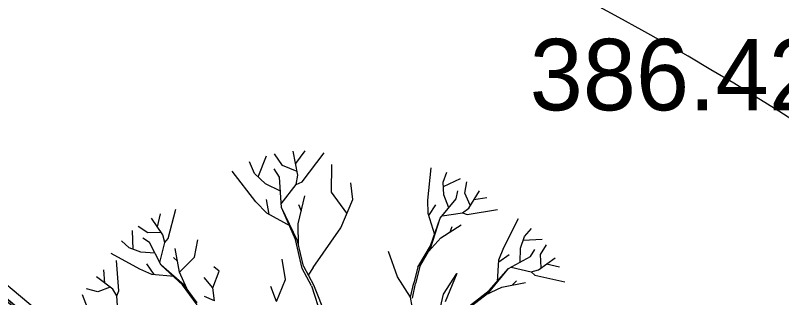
# Model space of a CAD drawing. Extents: x -438233 to -437334, y -1133133 to -1132623.
# Drawn here: x -438141.5 to -438133.46, y -1132955.36 to -1132952.39 of the extents above; entities that cross this region are included whole.
import ezdxf

# ---------------------------------------------------------------- set-up
doc = ezdxf.new("R2010")
doc.units = 0
for name, color, linetype in [('MOBILIÁŘ', 7, 'Continuous'), ('Vrstva 1', 7, 'Continuous'), ('Vrstva 10', 7, 'Continuous'), ('Vrstva 11', 7, 'Continuous'), ('Vrstva 3', 7, 'Continuous')]:
    doc.layers.add(name, color=color, linetype=linetype)

# ---------------------------------------------------------------- blocks, each defined once
blk = doc.blocks.new('A$C6FF56919')
at = {"layer": 'Vrstva 1'}
for p, q in [((-17605, 5482), (-17605, 7031)), ((-401, 7031), (-401, 5482)), ((0, 7031), (-401, 7031)), ((0, 5482), (0, 7031)), ((-18000, 5423), (-18000, 5482)), ((-18000, 5482), (-17605, 5482)), ((-18000, 5423), (0, 5423)), ((-18000, 5108), (-18000, 5423)), ((-18000, 5108), (0, 5108)), ((-18000, 4771), (-18000, 5108)), ((-17605, 5423), (-17605, 5482)), ((-401, 5482), (0, 5482)), ((-401, 5423), (-401, 5482)), ((0, 5423), (0, 5482)), ((0, 5423), (0, 5108)), ((0, 5108), (0, 4771)), ((-18000, 4771), (0, 4771)), ((-18000, 4707), (-18000, 4771)), ((0, 4707), (-18000, 4707)), ((-18000, 4707), (-18000, 4365)), ((-18000, 459), (-18000, 4365)), ((-18000, 4365), (0, 4365)), ((-17605, 459), (-17605, 4365)), ((-401, 459), (-401, 4365)), ((0, 4771), (0, 4707)), ((0, 4365), (0, 4707)), ((0, 459), (0, 4365)), ((-17605, 3703), (-17594, 3703)), ((-17594, 2805), (-17594, 3895)), ((-401, 3703), (-411, 3703)), ((-17605, 2907), (-17594, 2907)), ((-17605, 2901), (-17594, 2901)), ((-411, 2805), (-17594, 2805)), ((-17594, 2805), (-17594, 2762)), ((-17594, 2762), (-411, 2762)), ((-17594, 2575), (-411, 2575)), ((-17594, 1475), (-17594, 2575)), ((-9200, 2575), (-9200, 2762)), ((-8799, 2575), (-8799, 2762)), ((-401, 2907), (-411, 2907)), ((-401, 2901), (-411, 2901)), ((-411, 2762), (-411, 2805)), ((-411, 2575), (-411, 1475)), ((-17605, 2410), (-17594, 2410)), ((-401, 2410), (-411, 2410)), ((-17605, 1608), (-17594, 1608)), ((-17605, 1608), (-17594, 1608)), ((-17605, 1106), (-17594, 1106)), ((-17605, 1106), (-17594, 1106)), ((-17594, 1459), (-17594, 1475)), ((-17594, 1475), (-411, 1475)), ((-411, 1459), (-17594, 1459)), ((-17594, 1245), (-17594, 1256)), ((-17594, 1256), (-411, 1256)), ((-17594, 1245), (-17594, 144)), ((-411, 1245), (-17594, 1245)), ((-9200, 1256), (-9200, 1459)), ((-8800, 1256), (-8800, 1459)), ((-401, 1608), (-411, 1608)), ((-401, 1608), (-411, 1608)), ((-411, 1475), (-411, 1459)), ((-411, 1256), (-411, 1245)), ((-411, 144), (-411, 1245)), ((-401, 1106), (-411, 1106)), ((-401, 1106), (-411, 1106)), ((-18000, 459), (-18000, 0)), ((-17605, 459), (-18000, 459)), ((-18000, 0), (-17605, 0)), ((-17605, 0), (-17605, 459)), ((-17605, 305), (-17594, 305)), ((-17594, 144), (-411, 144)), ((-401, 305), (-411, 305)), ((-401, 459), (0, 459)), ((-401, 0), (-401, 459)), ((0, 0), (-401, 0)), ((0, 459), (0, 0))]:
    blk.add_line(p, q, dxfattribs=at)
for points in [[(-17605, 7031), (-18000, 7031), (-18000, 5482)], [(-17594, 3895), (-411, 3895), (-411, 2805)]]:
    blk.add_lwpolyline(points, dxfattribs=at)

msp = doc.modelspace()

# ---------------------------------------------------------------- linework, layer by layer
at = {"layer": 'Vrstva 1'}
for p, q in [((-438133.603, -1132953.391), (-438133.603, -1132953.391)), ((-438138.5371, -1132954.071), (-438138.5851, -1132953.8197)), ((-438138.5605, -1132953.9487), (-438138.461, -1132953.8167)), ((-438138.9534, -1132954.0908), (-438138.8676, -1132953.8689)), ((-438138.7003, -1132953.9703), (-438138.7812, -1132953.8473)), ((-438138.4939, -1132954.1406), (-438138.2612, -1132953.8359)), ((-438138.9923, -1132954.0536), (-438139.0463, -1132953.9331)), ((-438138.5461, -1132954.032), (-438138.7003, -1132953.9703)), ((-438138.1833, -1132954.2515), (-438138.1815, -1132953.9583)), ((-438138.9773, -1132954.3523), (-438139.2286, -1132954.0284)), ((-438138.8784, -1132954.1622), (-438138.9923, -1132954.0536)), ((-438138.7308, -1132954.0938), (-438138.7872, -1132954.0068)), ((-438137.1721, -1132954.3349), (-438137.1391, -1132953.996)), ((-438137.0101, -1132954.1454), (-438136.9741, -1132954.0416)), ((-438138.7105, -1132954.4105), (-438138.7308, -1132954.0938)), ((-438138.5539, -1132954.1688), (-438138.5371, -1132954.071)), ((-438138.5539, -1132954.1688), (-438138.4939, -1132954.1406)), ((-438137.0035, -1132954.2767), (-438137.0101, -1132954.1454)), ((-438137.0077, -1132954.1904), (-438136.829, -1132954.1052)), ((-438136.7852, -1132954.2617), (-438136.7648, -1132954.1412)), ((-438138.7212, -1132954.2408), (-438138.8784, -1132954.1622)), ((-438138.7123, -1132954.3721), (-438138.5539, -1132954.1688)), ((-438137.9602, -1132954.3259), (-438137.9829, -1132954.1508)), ((-438138.5329, -1132954.5844), (-438138.4628, -1132954.2887)), ((-438138.0219, -1132954.4717), (-438138.1833, -1132954.2515)), ((-438136.9526, -1132954.4147), (-438137.0035, -1132954.2767)), ((-438136.8752, -1132954.3199), (-438136.859, -1132954.2348)), ((-438136.7276, -1132954.3871), (-438136.7852, -1132954.2617)), ((-438136.7438, -1132954.4171), (-438136.6299, -1132954.2366)), ((-438136.6881, -1132954.3289), (-438136.5525, -1132954.3067)), ((-438138.8622, -1132954.4723), (-438138.9773, -1132954.3523)), ((-438138.8376, -1132954.4861), (-438138.867, -1132954.3259)), ((-438138.5005, -1132954.4489), (-438138.5275, -1132954.3835)), ((-438138.0873, -1132954.6246), (-438137.9602, -1132954.3259)), ((-438137.1709, -1132954.4735), (-438137.1721, -1132954.3349)), ((-438137.1631, -1132954.4968), (-438137.0899, -1132954.3823)), ((-438137.0431, -1132954.5232), (-438136.8752, -1132954.3199)), ((-438139.898, -1132954.738), (-438139.8206, -1132954.4273)), ((-438138.5617, -1132954.7481), (-438138.7105, -1132954.4105)), ((-438138.5425, -1132954.7601), (-438138.7105, -1132954.4105)), ((-438137.0227, -1132954.4992), (-438136.8104, -1132954.4663)), ((-438136.8104, -1132954.4663), (-438136.7438, -1132954.4171)), ((-438136.8104, -1132954.4663), (-438136.7582, -1132954.4843)), ((-438136.7582, -1132954.4843), (-438136.4422, -1132954.4315)), ((-438139.9538, -1132954.699), (-438140.0743, -1132954.5226)), ((-438140.0119, -1132954.6132), (-438139.9795, -1132954.4795)), ((-438138.6157, -1132954.6072), (-438138.8622, -1132954.4723)), ((-438137.0983, -1132954.6966), (-438137.1709, -1132954.4735)), ((-438137.1463, -1132954.8129), (-438137.0431, -1132954.5232)), ((-438137.1409, -1132954.8315), (-438137.0431, -1132954.5232)), ((-438136.3762, -1132954.8303), (-438136.2202, -1132954.5274)), ((-438140.1127, -1132954.6756), (-438140.2153, -1132954.609)), ((-438138.5311, -1132954.8099), (-438138.5329, -1132954.5844)), ((-438138.3782, -1132955.0426), (-438138.0873, -1132954.6246)), ((-438137.0353, -1132954.7302), (-438136.823, -1132954.5916)), ((-438136.9382, -1132954.6672), (-438136.9172, -1132954.612)), ((-438136.1561, -1132954.7146), (-438136.0835, -1132954.6306)), ((-438140.2656, -1132954.8513), (-438140.2734, -1132954.6534)), ((-438139.9741, -1132954.672), (-438140.1127, -1132954.6756)), ((-438139.9346, -1132954.7787), (-438139.9538, -1132954.699)), ((-438140.3082, -1132954.8357), (-438140.3892, -1132954.7613)), ((-438140.0941, -1132954.7799), (-438140.1667, -1132954.7326)), ((-438139.9741, -1132955.015), (-438140.0941, -1132954.7799)), ((-438139.9885, -1132954.9869), (-438139.9346, -1132954.7787)), ((-438139.9346, -1132954.7787), (-438139.898, -1132954.738)), ((-438139.6233, -1132954.9329), (-438139.5885, -1132954.7493)), ((-438138.4909, -1132955.0516), (-438138.5617, -1132954.7481)), ((-438138.4795, -1132955.0282), (-438138.5425, -1132954.7601)), ((-438137.1625, -1132954.8681), (-438137.0353, -1132954.7302)), ((-438136.1987, -1132954.8381), (-438136.1561, -1132954.7146)), ((-438136.1705, -1132954.7559), (-438135.9725, -1132954.7433)), ((-438140.1847, -1132954.8813), (-438140.3082, -1132954.8357)), ((-438139.7804, -1132955.09), (-438139.8242, -1132954.8405)), ((-438137.2764, -1132955.0372), (-438137.1463, -1132954.8129)), ((-438137.2572, -1132955.03), (-438137.1409, -1132954.8315)), ((-438136.4272, -1132954.9593), (-438136.3762, -1132954.8303)), ((-438136.2023, -1132954.9851), (-438136.1987, -1132954.8381)), ((-438136.0949, -1132954.9263), (-438136.0493, -1132954.8525)), ((-438135.9905, -1132954.9053), (-438135.9264, -1132954.8015)), ((-438140.1979, -1132955.0594), (-438140.4965, -1132954.8951)), ((-438140.0389, -1132954.8897), (-438140.1847, -1132954.8813)), ((-438139.8008, -1132954.9761), (-438139.8428, -1132954.9347)), ((-438139.7804, -1132955.09), (-438139.6233, -1132954.9329)), ((-438137.4905, -1132955.1386), (-438137.5853, -1132954.8735)), ((-438136.4284, -1132954.9833), (-438136.318, -1132954.9053)), ((-438136.3264, -1132955.0528), (-438136.0949, -1132954.9263)), ((-438136.0091, -1132955.0648), (-438135.8364, -1132954.9395)), ((-438135.9833, -1132955.0438), (-438135.9905, -1132954.9053)), ((-438140.4162, -1132955.2873), (-438140.4408, -1132954.9683)), ((-438140.0461, -1132955.1158), (-438140.1217, -1132955.0024)), ((-438139.7486, -1132955.2244), (-438139.9741, -1132955.015)), ((-438139.73, -1132955.2274), (-438139.9741, -1132955.015)), ((-438139.3654, -1132955.0792), (-438139.4188, -1132955.0324)), ((-438138.6667, -1132955.1674), (-438138.7015, -1132954.9545)), ((-438138.4795, -1132955.0282), (-438138.374, -1132955.2226)), ((-438137.2572, -1132955.03), (-438137.3034, -1132955.2076)), ((-438136.4428, -1132955.1932), (-438136.4272, -1132954.9593)), ((-438135.9252, -1132955.0042), (-438135.7908, -1132955.033)), ((-438140.5643, -1132955.2052), (-438140.5757, -1132955.0672)), ((-438140.0701, -1132955.1134), (-438140.1979, -1132955.0594)), ((-438139.8368, -1132955.1344), (-438140.0701, -1132955.1134)), ((-438139.7043, -1132955.2615), (-438139.7804, -1132955.09)), ((-438139.432, -1132955.2549), (-438139.3654, -1132955.0792)), ((-438138.3926, -1132955.2322), (-438138.4909, -1132955.0516)), ((-438138.3782, -1132955.0426), (-438138.4286, -1132955.123)), ((-438137.2764, -1132955.0372), (-438137.3202, -1132955.2034)), ((-438137.0089, -1132955.3215), (-438136.8686, -1132955.1056)), ((-438136.8686, -1132955.1056), (-438136.9891, -1132955.4031)), ((-438136.5321, -1132955.3023), (-438136.3264, -1132955.0528)), ((-438136.5303, -1132955.2831), (-438136.3264, -1132955.0528)), ((-438136.2988, -1132955.0372), (-438136.0889, -1132955.0864)), ((-438136.0889, -1132955.0864), (-438136.0091, -1132955.0648)), ((-438136.0889, -1132955.0864), (-438136.0475, -1132955.1212)), ((-438140.4815, -1132955.2675), (-438140.6513, -1132955.1386)), ((-438139.432, -1132955.2549), (-438139.5219, -1132955.1452)), ((-438138.762, -1132955.3995), (-438138.6667, -1132955.1674)), ((-438137.3544, -1132955.3539), (-438137.4905, -1132955.1386)), ((-438136.282, -1132955.2244), (-438136.2424, -1132955.1812)), ((-438136.0475, -1132955.1212), (-438135.735, -1132955.1908)), ((-438140.6393, -1132955.2957), (-438140.7574, -1132955.2651)), ((-438140.5085, -1132955.2489), (-438140.6393, -1132955.2957)), ((-438140.4378, -1132955.3377), (-438140.4815, -1132955.2675)), ((-438139.5945, -1132955.4337), (-438139.7486, -1132955.2244)), ((-438139.5933, -1132955.4121), (-438139.73, -1132955.2274)), ((-438139.4116, -1132955.3905), (-438139.432, -1132955.2549)), ((-438138.762, -1132955.3995), (-438138.8226, -1132955.24)), ((-438138.3926, -1132955.2322), (-438138.2528, -1132955.6754)), ((-438138.374, -1132955.2226), (-438138.227, -1132955.5896)), ((-438137.3544, -1132955.3539), (-438137.3202, -1132955.2034)), ((-438137.3322, -1132955.3623), (-438137.3034, -1132955.2076)), ((-438136.5663, -1132955.3287), (-438136.396, -1132955.2483)), ((-438136.396, -1132955.2483), (-438136.1477, -1132955.1974)), ((-438140.7298, -1132955.5116), (-438140.7994, -1132955.3263)), ((-438140.4378, -1132955.3377), (-438140.4162, -1132955.2873)), ((-438140.4234, -1132955.553), (-438140.4378, -1132955.3377)), ((-438139.4116, -1132955.3905), (-438139.5171, -1132955.3455)), ((-438137.3088, -1132955.6112), (-438137.3544, -1132955.3539)), ((-438137.0821, -1132955.6466), (-438137.0089, -1132955.3215)), ((-438136.7348, -1132955.4433), (-438136.5303, -1132955.2831)), ((-438136.7133, -1132955.4445), (-438136.5321, -1132955.3023))]:
    msp.add_line(p, q, dxfattribs=at)
msp.add_arc((-438145.7064, -1132959.3531), 11.8615, 67.16775, 153.12947, dxfattribs=at)
at = {"layer": 'Vrstva 10'}
msp.add_arc((-438148.1382, -1132975.8912), 28.8654, 47.35444, 91.79822, dxfattribs=at)
at = {"layer": 'Vrstva 11'}
msp.add_arc((-438148.8455, -1132977.7142), 28.7583, 48.80603, 84.36153, dxfattribs=at)

# ---------------------------------------------------------------- block references
at = {"layer": 'MOBILIÁŘ', "xscale": 9.999999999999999e-05, "yscale": 0.0001, "rotation": 140.2266867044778}
msp.add_blockref('A$C6FF56919', (-438142.4453, -1132954.4972), dxfattribs=at)

# ---------------------------------------------------------------- texts
at = {"layer": 'Vrstva 3'}
msp.add_text('386.42 ', height=0.75, dxfattribs=at).set_placement((-438136.103, -1132953.391))

doc.saveas('drawing.dxf')
